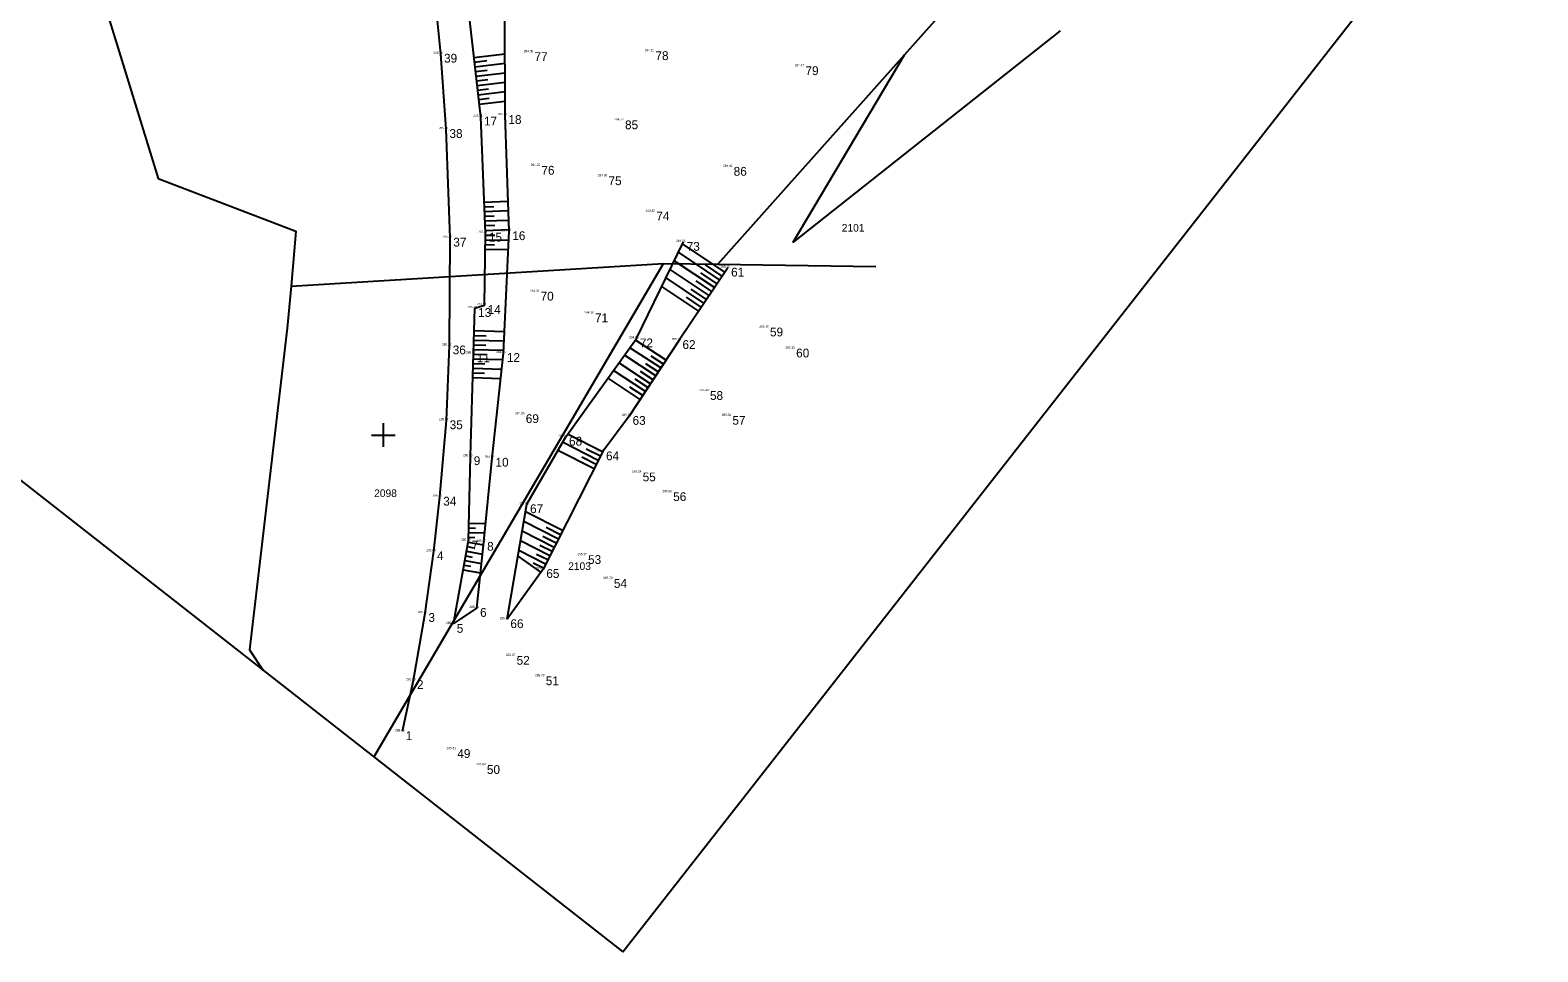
# Model space of a CAD drawing. Extents: x -594197 to -593885, y -1138044 to -1137704.
# Drawn here: x -594130.1 to -594001.7, y -1138044 to -1137965.5 of the extents above; entities that cross this region are included whole.
import ezdxf

# ---------------------------------------------------------------- set-up
doc = ezdxf.new("R2010")
doc.units = 0
for name, color, linetype in [('Katastrální mapa', 7, 'Continuous'), ('Ploty', 7, 'Continuous'), ('Podrobný bod', 7, 'Continuous'), ('Podrobný bod výška', 7, 'Continuous'), ('Podrobný bod číslo', 7, 'Continuous'), ('Ram mapoveho listu', 7, 'Continuous'), ('Rozhraní ploch', 7, 'Continuous'), ('Výškopis', 7, 'Continuous'), ('Výškopis šrafy', 7, 'Continuous'), ('Čtvercová síť', 7, 'Continuous')]:
    doc.layers.add(name, color=color, linetype=linetype)

msp = doc.modelspace()

# ---------------------------------------------------------------- linework, layer by layer
at = {"layer": 'Katastrální mapa'}
for p, q in [((-594071.52, -1137985.45), (-594055.62, -1137967.61)), ((-594107.86, -1137987.33), (-594076.14, -1137985.38)), ((-594100.8, -1138027.42), (-594076.14, -1137985.38)), ((-594076.14, -1137985.38), (-594071.52, -1137985.45)), ((-594071.52, -1137985.45), (-594058.08, -1137985.65))]:
    msp.add_line(p, q, dxfattribs=at)
for points in [[(-594055.62, -1137967.61), (-594043.39, -1137953.89), (-594020.92, -1137938.17)], [(-594123.89, -1137962.84), (-594119.16, -1137978.15), (-594107.44, -1137982.65), (-594107.86, -1137987.33)], [(-594042.37, -1137965.58), (-594065.12, -1137983.59), (-594055.62, -1137967.61)], [(-594107.86, -1137987.33), (-594108.19, -1137990.9), (-594111.4, -1138018.3), (-594110.24, -1138020.04)]]:
    msp.add_lwpolyline(points, dxfattribs=at)
at = {"layer": 'Ploty'}
msp.add_lwpolyline([(-594070.67, -1137985.75), (-594074.81, -1137991.92), (-594079.06, -1137998.38), (-594081.32, -1138001.4)], dxfattribs=at)
at = {"layer": 'Podrobný bod'}
for p, q in [((-594095.11, -1137967.54), (-594095.11, -1137967.54)), ((-594087.41, -1137967.4), (-594087.41, -1137967.4)), ((-594077.11, -1137967.32), (-594077.11, -1137967.32)), ((-594064.34, -1137968.6), (-594064.34, -1137968.6)), ((-594091.71, -1137972.89), (-594091.71, -1137972.89)), ((-594089.63, -1137972.76), (-594089.63, -1137972.76)), ((-594079.7, -1137973.21), (-594079.7, -1137973.21)), ((-594094.65, -1137973.95), (-594094.65, -1137973.95)), ((-594086.82, -1137977.08), (-594086.82, -1137977.08)), ((-594081.11, -1137977.97), (-594081.11, -1137977.97)), ((-594070.45, -1137977.17), (-594070.45, -1137977.17)), ((-594077.04, -1137980.98), (-594077.04, -1137980.98)), ((-594094.32, -1137983.2), (-594094.32, -1137983.2)), ((-594091.29, -1137982.78), (-594091.29, -1137982.78)), ((-594089.3, -1137982.65), (-594089.3, -1137982.65)), ((-594074.45, -1137983.56), (-594074.45, -1137983.56)), ((-594070.67, -1137985.75), (-594070.67, -1137985.75)), ((-594086.89, -1137987.8), (-594086.89, -1137987.8)), ((-594092.21, -1137989.19), (-594092.21, -1137989.19)), ((-594091.4, -1137988.94), (-594091.4, -1137988.94)), ((-594082.26, -1137989.65), (-594082.26, -1137989.65)), ((-594067.36, -1137990.85), (-594067.36, -1137990.85)), ((-594094.37, -1137992.38), (-594094.37, -1137992.38)), ((-594078.44, -1137991.78), (-594078.44, -1137991.78)), ((-594074.81, -1137991.92), (-594074.81, -1137991.92)), ((-594092.32, -1137993.06), (-594092.32, -1137993.06)), ((-594089.76, -1137993.02), (-594089.76, -1137993.02)), ((-594065.13, -1137992.64), (-594065.13, -1137992.64)), ((-594072.47, -1137996.26), (-594072.47, -1137996.26)), ((-594094.63, -1137998.75), (-594094.63, -1137998.75)), ((-594088.15, -1137998.23), (-594088.15, -1137998.23)), ((-594079.06, -1137998.38), (-594079.06, -1137998.38)), ((-594070.56, -1137998.37), (-594070.56, -1137998.37)), ((-594084.47, -1138000.15), (-594084.47, -1138000.15)), ((-594081.32, -1138001.4), (-594081.32, -1138001.4)), ((-594092.58, -1138001.81), (-594092.58, -1138001.81)), ((-594090.73, -1138001.94), (-594090.73, -1138001.94)), ((-594078.2, -1138003.19), (-594078.2, -1138003.19)), ((-594095.18, -1138005.26), (-594095.18, -1138005.26)), ((-594075.6, -1138004.87), (-594075.6, -1138004.87)), ((-594087.79, -1138005.9), (-594087.79, -1138005.9)), ((-594092.75, -1138008.99), (-594092.75, -1138008.99)), ((-594091.44, -1138009.1), (-594091.44, -1138009.1)), ((-594095.71, -1138009.9), (-594095.71, -1138009.9)), ((-594082.85, -1138010.23), (-594082.85, -1138010.23)), ((-594086.4, -1138011.42), (-594086.4, -1138011.42)), ((-594080.65, -1138012.26), (-594080.65, -1138012.26)), ((-594096.44, -1138015.16), (-594096.44, -1138015.16)), ((-594092.04, -1138014.73), (-594092.04, -1138014.73)), ((-594094.03, -1138016.09), (-594094.03, -1138016.09)), ((-594089.46, -1138015.69), (-594089.46, -1138015.69)), ((-594088.93, -1138018.81), (-594088.93, -1138018.81)), ((-594086.45, -1138020.55), (-594086.45, -1138020.55)), ((-594097.42, -1138020.88), (-594097.42, -1138020.88)), ((-594098.37, -1138025.23), (-594098.37, -1138025.23)), ((-594093.98, -1138026.75), (-594093.98, -1138026.75)), ((-594091.46, -1138028.11), (-594091.46, -1138028.11))]:
    msp.add_line(p, q, dxfattribs=at)
at = {"layer": 'Ram mapoveho listu'}
for p, q in [((-594079.6, -1138044.01), (-593885.47, -1137795.94)), ((-594196.55, -1137952.49), (-594079.6, -1138044.01))]:
    msp.add_line(p, q, dxfattribs=at)
at = {"layer": 'Rozhraní ploch'}
msp.add_lwpolyline([(-594098.37, -1138025.23), (-594097.42, -1138020.88), (-594096.44, -1138015.16), (-594095.71, -1138009.9), (-594095.18, -1138005.26), (-594094.63, -1137998.75), (-594094.37, -1137992.38), (-594094.32, -1137983.2), (-594094.65, -1137973.95), (-594095.11, -1137967.54), (-594095.75, -1137960.98), (-594097.41, -1137943.93), (-594098.5, -1137932.77), (-594099.57, -1137922.21), (-594100.64, -1137910.93), (-594102.1, -1137896.65), (-594103.58, -1137881.21), (-594104.68, -1137869.94), (-594106.08, -1137856.13)], dxfattribs=at)
at = {"layer": 'Výškopis'}
for points in [[(-594094.03, -1138016.09), (-594092.75, -1138008.99), (-594092.58, -1138001.81), (-594092.32, -1137993.06), (-594092.21, -1137989.19), (-594091.4, -1137988.94), (-594091.29, -1137982.78), (-594091.71, -1137972.89), (-594092.65, -1137964.7), (-594093.07, -1137953.09), (-594092.96, -1137947.37), (-594088.47, -1137942.64), (-594086.31, -1137941.28), (-594082.24, -1137941.08), (-594077.7, -1137942.35)], [(-594094.03, -1138016.09), (-594092.04, -1138014.73), (-594091.44, -1138009.1), (-594090.73, -1138001.94), (-594089.76, -1137993.02), (-594089.3, -1137982.65), (-594089.63, -1137972.76), (-594089.65, -1137964.05), (-594090.61, -1137952.66), (-594089.87, -1137949.62), (-594087.68, -1137948.29), (-594086.78, -1137947.12), (-594085.93, -1137944.87), (-594085.89, -1137943.37), (-594081.18, -1137943.01), (-594077.7, -1137942.35)], [(-594089.46, -1138015.69), (-594087.79, -1138005.9), (-594084.47, -1138000.15), (-594078.44, -1137991.78), (-594074.45, -1137983.56)], [(-594081.32, -1138001.4), (-594086.4, -1138011.42), (-594089.46, -1138015.69)]]:
    msp.add_lwpolyline(points, dxfattribs=at)
at = {"layer": 'Výškopis šrafy'}
for p, q in [((-594092.29, -1137967.84), (-594089.64, -1137967.54)), ((-594092.24, -1137968.24), (-594091.2, -1137968.12)), ((-594092.2, -1137968.64), (-594089.64, -1137968.34)), ((-594092.15, -1137969.03), (-594091.15, -1137968.92)), ((-594092.11, -1137969.43), (-594089.64, -1137969.15)), ((-594092.06, -1137969.83), (-594091.09, -1137969.72)), ((-594092.02, -1137970.23), (-594089.64, -1137969.95)), ((-594091.97, -1137970.62), (-594091.04, -1137970.52)), ((-594091.92, -1137971.02), (-594089.63, -1137970.76)), ((-594091.88, -1137971.42), (-594090.98, -1137971.32)), ((-594091.83, -1137971.82), (-594089.63, -1137971.56)), ((-594091.4, -1137980.17), (-594089.39, -1137980.09)), ((-594091.38, -1137980.57), (-594090.58, -1137980.54)), ((-594091.37, -1137980.97), (-594089.36, -1137980.89)), ((-594091.35, -1137981.37), (-594090.55, -1137981.34)), ((-594091.33, -1137981.77), (-594089.33, -1137981.69)), ((-594091.32, -1137982.17), (-594090.52, -1137982.14)), ((-594091.3, -1137982.57), (-594089.31, -1137982.49)), ((-594091.3, -1137983.37), (-594089.33, -1137983.41)), ((-594091.29, -1137982.97), (-594090.5, -1137982.99)), ((-594091.31, -1137983.77), (-594090.53, -1137983.79)), ((-594091.31, -1137984.17), (-594089.37, -1137984.21)), ((-594071.37, -1137986.79), (-594074.88, -1137984.44)), ((-594070.92, -1137986.13), (-594074.52, -1137983.71)), ((-594072.26, -1137988.12), (-594075.58, -1137985.89)), ((-594071.81, -1137987.45), (-594075.23, -1137985.16)), ((-594071.14, -1137986.46), (-594072.57, -1137985.5)), ((-594073.15, -1137989.45), (-594076.29, -1137987.34)), ((-594072.7, -1137988.78), (-594075.93, -1137986.62)), ((-594072.04, -1137987.79), (-594073.38, -1137986.88)), ((-594071.59, -1137987.12), (-594072.97, -1137986.19)), ((-594072.93, -1137989.11), (-594074.2, -1137988.26)), ((-594072.48, -1137988.45), (-594073.79, -1137987.57)), ((-594092.26, -1137991.11), (-594089.68, -1137991.18)), ((-594092.3, -1137992.31), (-594091.27, -1137992.34)), ((-594092.29, -1137991.91), (-594089.71, -1137991.98)), ((-594092.28, -1137991.51), (-594091.24, -1137991.54)), ((-594075.93, -1137993.62), (-594078.53, -1137991.91)), ((-594092.33, -1137993.51), (-594089.82, -1137993.58)), ((-594092.32, -1137993.11), (-594091.3, -1137993.14)), ((-594092.31, -1137992.71), (-594089.75, -1137992.78)), ((-594076.81, -1137994.96), (-594079.47, -1137993.21)), ((-594076.37, -1137994.29), (-594079, -1137992.56)), ((-594076.15, -1137993.96), (-594077.2, -1137993.27)), ((-594092.37, -1137994.71), (-594091.4, -1137994.74)), ((-594092.36, -1137994.31), (-594089.91, -1137994.38)), ((-594092.35, -1137993.91), (-594091.35, -1137993.94)), ((-594077.69, -1137996.29), (-594080.4, -1137994.51)), ((-594077.25, -1137995.63), (-594079.94, -1137993.86)), ((-594077.03, -1137995.29), (-594078.1, -1137994.59)), ((-594076.59, -1137994.62), (-594077.65, -1137993.93)), ((-594092.38, -1137995.11), (-594089.99, -1137995.18)), ((-594078.13, -1137996.96), (-594080.87, -1137995.16)), ((-594077.91, -1137996.63), (-594079, -1137995.91)), ((-594077.47, -1137995.96), (-594078.55, -1137995.25)), ((-594081.34, -1138001.44), (-594084.31, -1137999.93)), ((-594082.06, -1138002.87), (-594085.14, -1138001.31)), ((-594081.7, -1138002.16), (-594084.74, -1138000.62)), ((-594081.52, -1138001.8), (-594082.73, -1138001.19)), ((-594081.88, -1138002.51), (-594083.11, -1138001.89)), ((-594084.74, -1138008.14), (-594087.9, -1138006.54)), ((-594092.71, -1138007.51), (-594091.29, -1138007.54)), ((-594085.1, -1138008.86), (-594088.04, -1138007.37)), ((-594084.92, -1138008.5), (-594086.14, -1138007.88)), ((-594092.77, -1138009.11), (-594091.47, -1138009.34)), ((-594092.74, -1138008.71), (-594092.21, -1138008.72)), ((-594092.73, -1138008.31), (-594091.36, -1138008.34)), ((-594092.72, -1138007.91), (-594092.16, -1138007.92)), ((-594085.82, -1138010.28), (-594088.32, -1138009.02)), ((-594085.46, -1138009.57), (-594088.18, -1138008.19)), ((-594085.28, -1138009.21), (-594086.41, -1138008.64)), ((-594092.98, -1138010.29), (-594092.43, -1138010.39)), ((-594092.91, -1138009.89), (-594091.55, -1138010.14)), ((-594092.84, -1138009.5), (-594092.31, -1138009.6)), ((-594086.59, -1138011.68), (-594088.54, -1138010.29)), ((-594086.19, -1138011), (-594088.46, -1138009.84)), ((-594086, -1138010.64), (-594086.96, -1138010.16)), ((-594085.64, -1138009.93), (-594086.69, -1138009.4)), ((-594093.2, -1138011.47), (-594091.72, -1138011.73)), ((-594093.13, -1138011.07), (-594092.55, -1138011.18)), ((-594093.05, -1138010.68), (-594091.64, -1138010.94)), ((-594086.37, -1138011.35), (-594087.23, -1138010.91))]:
    msp.add_line(p, q, dxfattribs=at)
at = {"layer": 'Čtvercová síť'}
for p, q in [((-594101, -1138000), (-594099, -1138000)), ((-594100, -1138001), (-594100, -1137999))]:
    msp.add_line(p, q, dxfattribs=at)

# ---------------------------------------------------------------- texts
at = {"layer": 'Katastrální mapa'}
for s, p in [('2101', (-594060.97, -1137982.68)), ('2098', (-594100.78, -1138005.28)), ('2103', (-594084.26, -1138011.49))]:
    msp.add_text(s, height=0.65, dxfattribs=at).set_placement(p)
at = {"layer": 'Podrobný bod výška'}
for s, p in [('285.46 ', (-594095.74, -1137967.54)), ('284.08 ', (-594088.04, -1137967.4)), ('284.21 ', (-594077.74, -1137967.32)), ('284.47 ', (-594064.97, -1137968.6)), ('285.31 ', (-594092.34, -1137972.89)), ('284.23 ', (-594090.26, -1137972.76)), ('284.22 ', (-594080.33, -1137973.21)), ('285.46 ', (-594095.28, -1137973.95)), ('284.22 ', (-594087.45, -1137977.08)), ('284.46 ', (-594071.08, -1137977.17)), ('284.30 ', (-594081.74, -1137977.97)), ('284.42 ', (-594077.67, -1137980.98)), ('285.46 ', (-594094.95, -1137983.2)), ('285.31 ', (-594091.92, -1137982.78)), ('284.44 ', (-594089.93, -1137982.65)), ('284.56 ', (-594075.08, -1137983.56)), ('285.36 ', (-594071.3, -1137985.75)), ('284.33 ', (-594087.52, -1137987.8)), ('285.38 ', (-594092.84, -1137989.19)), ('285.29 ', (-594092.03, -1137988.94)), ('284.38 ', (-594082.89, -1137989.65)), ('285.40 ', (-594067.99, -1137990.85)), ('285.52 ', (-594095, -1137992.38)), ('284.53 ', (-594079.07, -1137991.78)), ('285.36 ', (-594075.44, -1137991.92)), ('285.33 ', (-594065.76, -1137992.64)), ('285.37 ', (-594092.95, -1137993.06)), ('284.45 ', (-594090.39, -1137993.02)), ('285.49 ', (-594073.1, -1137996.26)), ('285.57 ', (-594095.26, -1137998.75)), ('284.36 ', (-594088.78, -1137998.23)), ('285.37 ', (-594079.69, -1137998.38)), ('285.38 ', (-594071.19, -1137998.37)), ('284.53 ', (-594085.1, -1138000.15)), ('285.32 ', (-594081.95, -1138001.4)), ('285.49 ', (-594093.21, -1138001.81)), ('284.76 ', (-594091.36, -1138001.94)), ('285.54 ', (-594078.83, -1138003.19)), ('285.61 ', (-594095.81, -1138005.26)), ('285.56 ', (-594076.23, -1138004.87)), ('284.81 ', (-594088.42, -1138005.9)), ('285.59 ', (-594093.38, -1138008.99)), ('285.17 ', (-594092.07, -1138009.1)), ('285.64 ', (-594096.34, -1138009.9)), ('285.57 ', (-594083.48, -1138010.23)), ('285.57 ', (-594087.03, -1138011.42)), ('285.70 ', (-594081.28, -1138012.26)), ('285.66 ', (-594097.07, -1138015.16)), ('285.49 ', (-594092.67, -1138014.73)), ('285.61 ', (-594090.09, -1138015.69)), ('285.63 ', (-594094.66, -1138016.09)), ('285.67 ', (-594089.56, -1138018.81)), ('285.69 ', (-594098.05, -1138020.88)), ('285.78 ', (-594087.08, -1138020.55)), ('285.80 ', (-594099, -1138025.23)), ('285.81 ', (-594094.61, -1138026.75)), ('285.84 ', (-594092.09, -1138028.11))]:
    msp.add_text(s, height=0.188, dxfattribs=at).set_placement(p)
at = {"layer": 'Podrobný bod číslo'}
for s, p in [(' 39', (-594095.11, -1137968.29)), (' 77', (-594087.41, -1137968.15)), (' 78', (-594077.11, -1137968.07)), (' 79', (-594064.34, -1137969.35)), (' 17', (-594091.71, -1137973.64)), (' 18', (-594089.63, -1137973.51)), (' 85', (-594079.7, -1137973.96)), (' 38', (-594094.65, -1137974.7)), (' 76', (-594086.82, -1137977.83)), (' 75', (-594081.11, -1137978.72)), (' 86', (-594070.45, -1137977.92)), (' 74', (-594077.04, -1137981.73)), (' 37', (-594094.32, -1137983.95)), (' 15', (-594091.29, -1137983.53)), (' 16', (-594089.3, -1137983.4)), (' 73', (-594074.45, -1137984.31)), (' 61', (-594070.67, -1137986.5)), (' 70', (-594086.89, -1137988.55)), (' 13', (-594092.21, -1137989.94)), (' 14', (-594091.4, -1137989.69)), (' 71', (-594082.26, -1137990.4)), (' 59', (-594067.36, -1137991.6)), (' 36', (-594094.37, -1137993.13)), (' 72', (-594078.44, -1137992.53)), (' 62', (-594074.81, -1137992.67)), (' 11', (-594092.32, -1137993.81)), (' 12', (-594089.76, -1137993.77)), (' 60', (-594065.13, -1137993.39)), (' 58', (-594072.47, -1137997.01)), (' 35', (-594094.63, -1137999.5)), (' 69', (-594088.15, -1137998.98)), (' 63', (-594079.06, -1137999.13)), (' 57', (-594070.56, -1137999.12)), (' 68', (-594084.47, -1138000.9)), (' 64', (-594081.32, -1138002.15)), (' 9', (-594092.58, -1138002.56)), (' 10', (-594090.73, -1138002.69)), (' 55', (-594078.2, -1138003.94)), (' 34', (-594095.18, -1138006.01)), (' 56', (-594075.6, -1138005.62)), (' 67', (-594087.79, -1138006.65)), (' 7', (-594092.75, -1138009.74)), (' 8', (-594091.44, -1138009.85)), (' 4', (-594095.71, -1138010.65)), (' 53', (-594082.85, -1138010.98)), (' 65', (-594086.4, -1138012.17)), (' 54', (-594080.65, -1138013.01)), (' 3', (-594096.44, -1138015.91)), (' 6', (-594092.04, -1138015.48)), (' 5', (-594094.03, -1138016.84)), (' 66', (-594089.46, -1138016.44)), (' 52', (-594088.93, -1138019.56)), (' 51', (-594086.45, -1138021.3)), (' 2', (-594097.42, -1138021.63)), (' 1', (-594098.37, -1138025.98)), (' 49', (-594093.98, -1138027.5)), (' 50', (-594091.46, -1138028.86))]:
    msp.add_text(s, height=0.75, dxfattribs=at).set_placement(p)

doc.saveas('drawing.dxf')
